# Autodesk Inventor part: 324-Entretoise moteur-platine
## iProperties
Author: Philippe
Created: 2001-12
Part Number: 324-Entretoise moteur-platine
Material: Par défaut
Document SubType Name: Modélisation
Designer: Philippe
Control State: 0
Master: False
Checked Out: False
PropertySet Name: Design Tracking Control
Shininess: 69.0
Angle Display Precision: 2
Document Length Units: 11269
Document Angle Units: 11283
Document Time Units: 11279
Document Mass Units: 11290
Document Length Units Precision: 3
Document Angle Units Precision: 2
Compacted: False
PropertySet Name: _Private Model Information
Density: 0.0
Volumn: 0.0
Area: 0.0
PropertySet Name: Model Information
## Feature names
1. Révolution1 [Revolution]
